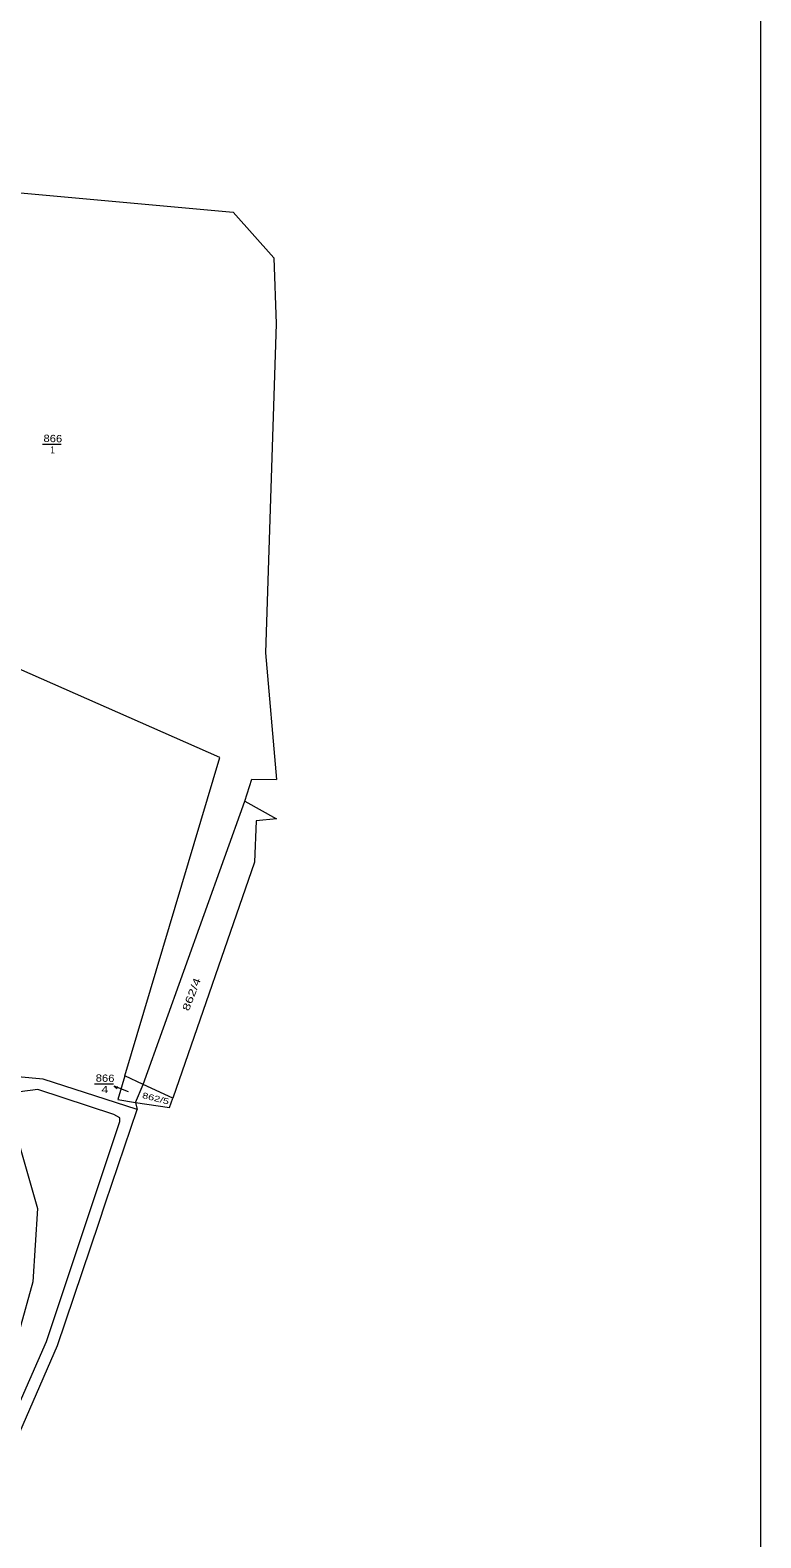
# Model space of a CAD drawing. Extents: x -843400 to -842830, y -1002860 to -1002082.
# Drawn here: x -842930.2 to -842830.1, y -1002726.5 to -1002520 of the extents above; entities that cross this region are included whole.
import ezdxf
from ezdxf.enums import TextEntityAlignment as Align

# ---------------------------------------------------------------- set-up
doc = ezdxf.new("R2010")
doc.units = 0
doc.header["$LTSCALE"] = 0.4
for name, color, linetype, lineweight in [('32', 7, 'Continuous', 13), ('34', 7, 'Continuous', 13), ('40', 7, 'Continuous', 13), ('43', 7, 'Continuous', 13), ('44', 7, 'Continuous', 13)]:
    doc.layers.add(name, color=color, linetype=linetype, lineweight=lineweight)

msp = doc.modelspace()

# ---------------------------------------------------------------- linework, layer by layer
at = {"layer": '32'}
for p, q in [((-842900.82, -1002625.56), (-842896.47, -1002627.98)), ((-842899.48, -1002633.92), (-842910.67, -1002666.23)), ((-842915.8, -1002666.84), (-842915.57, -1002667.81))]:
    msp.add_line(p, q, dxfattribs=at)
for points in [[(-842917.26, -1002663.21), (-842904.25, -1002619.58), (-842968.69, -1002591.19), (-842954.99, -1002566.47), (-842952.01, -1002568.05), (-842939.57, -1002549.22), (-842952.33, -1002528.36), (-842968.38, -1002501.67), (-842999.65, -1002478.78), (-842992.16, -1002464.73), (-842985.04, -1002466.11)], [(-842914.71, -1002664.38), (-842900.82, -1002625.56), (-842899.85, -1002622.58), (-842896.46, -1002622.59)], [(-842896.47, -1002627.98), (-842899.25, -1002628.26), (-842899.48, -1002633.92)], [(-842949.73, -1002770.53), (-842948.12, -1002770.28), (-842947.09, -1002769.45), (-842946.99, -1002769.3), (-842946.43, -1002768.26), (-842946.36, -1002766.94), (-842947.25, -1002754.97), (-842947.02, -1002748.98), (-842946.95, -1002748.51), (-842945.3, -1002742.1), (-842942.37, -1002735.33), (-842934.56, -1002718.61), (-842926.46, -1002700.13), (-842920.81, -1002683.35), (-842919.88, -1002680.59), (-842915.57, -1002667.81), (-842928.42, -1002663.65), (-842931.89, -1002663.34)], [(-842915.8, -1002666.84), (-842911.12, -1002667.52), (-842910.67, -1002666.23), (-842914.71, -1002664.38)]]:
    msp.add_lwpolyline(points, dxfattribs=at)
msp.add_lwpolyline([(-842915.8, -1002666.84), (-842914.71, -1002664.38), (-842917.26, -1002663.21), (-842918.22, -1002666.44)], close=True, dxfattribs=at)
at = {"layer": '34'}
for p, q in [((-842928.548, -1002576.7), (-842925.952, -1002576.7)), ((-842921.391, -1002664.308), (-842918.795, -1002664.308)), ((-842918.704, -1002664.626), (-842918.311, -1002664.916))]:
    msp.add_line(p, q, dxfattribs=at)
msp.add_lwpolyline([(-842916.75, -1002665.395), (-842918.704, -1002664.626), (-842918.218, -1002664.682)], dxfattribs=at)
at = {"layer": '40'}
msp.add_lwpolyline([(-843160.48, -1002346.53), (-843130.91, -1002349.42), (-843135.89, -1002376.13), (-843137.14, -1002382.83), (-843106.81, -1002397.6), (-843074.76, -1002421.55), (-843056.97, -1002434.86), (-843014.68, -1002358.16), (-842987.77, -1002367.07), (-842967.67, -1002372.97), (-842947.11, -1002381.03), (-842989.7, -1002460.5), (-842985.04, -1002466.11), (-842976.06, -1002481.3), (-842960.58, -1002507.03), (-842950.97, -1002527.42), (-842942.15, -1002541.29), (-842902.4, -1002544.91), (-842896.82, -1002551.16), (-842896.49, -1002560.21), (-842897.95, -1002605.27), (-842896.46, -1002622.59)], dxfattribs=at)
at = {"layer": '43'}
msp.add_lwpolyline([(-842948.56, -1002768.3), (-842947.94, -1002767.12), (-842948.92, -1002755.12), (-842948.68, -1002748.71), (-842946.84, -1002741.5), (-842943.78, -1002734.66), (-842936.02, -1002717.81), (-842928, -1002699.57), (-842922.39, -1002682.86), (-842917.91, -1002669.43), (-842917.91, -1002668.95), (-842918.75, -1002668.47), (-842929.16, -1002665.07), (-842931.62, -1002665.4), (-842933.52, -1002666.36), (-842929.19, -1002681.38), (-842929.83, -1002691.39), (-842931.73, -1002698.15), (-842939.66, -1002716.51), (-842946.75, -1002733.04), (-842949.38, -1002740.61), (-842950.88, -1002748.67), (-842951.06, -1002754.94), (-842949.88, -1002768.58)], close=True, dxfattribs=at)
at = {"layer": '44'}
msp.add_lwpolyline([(-842830.097, -1002859.997), (-842830.097, -1002081.989), (-843400.094, -1002081.989), (-843400.094, -1002859.997)], close=True, dxfattribs=at)

# ---------------------------------------------------------------- texts
at = {"layer": '34'}
for s, height, rotation, width, p in [('866', 1, 358.734, 1.15, (-842927.118, -1002576.4026)), ('1', 1, 358.734, 0.7, (-842927.1535, -1002577.9528)), ('862/4', 1, 69.046, 1.4, (-842907.6472, -1002652.2158)), ('866', 1, 358.734, 1.15, (-842919.962, -1002664.0106)), ('4', 1, 358.734, 1.25, (-842919.9965, -1002665.5604)), ('862/5', 0.8, 345.706, 1.4, (-842913.1148, -1002666.6728))]:
    msp.add_text(s, height=height, rotation=rotation, dxfattribs=dict(at, width=width)).set_placement(p, align=Align.CENTER)

doc.saveas('drawing.dxf')
